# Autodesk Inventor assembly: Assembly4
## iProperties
Shininess: 64.0
Length Units: 11269
Angle Units: 11279
Time Units: 11290
Mass Units: 11283
Length Display Precision: 3
Angle Display Precision: 2
Compacted: True
Created: 2003-01
Part Number: Assembly4
Document SubType Name: Weldment
Designer: Owner
Density: 0.0
Volumn: 0.0
Area: 0.0
PropertySet Name: Model Information
Control State: 0
Master: False
Checked Out: False
Author: Owner
